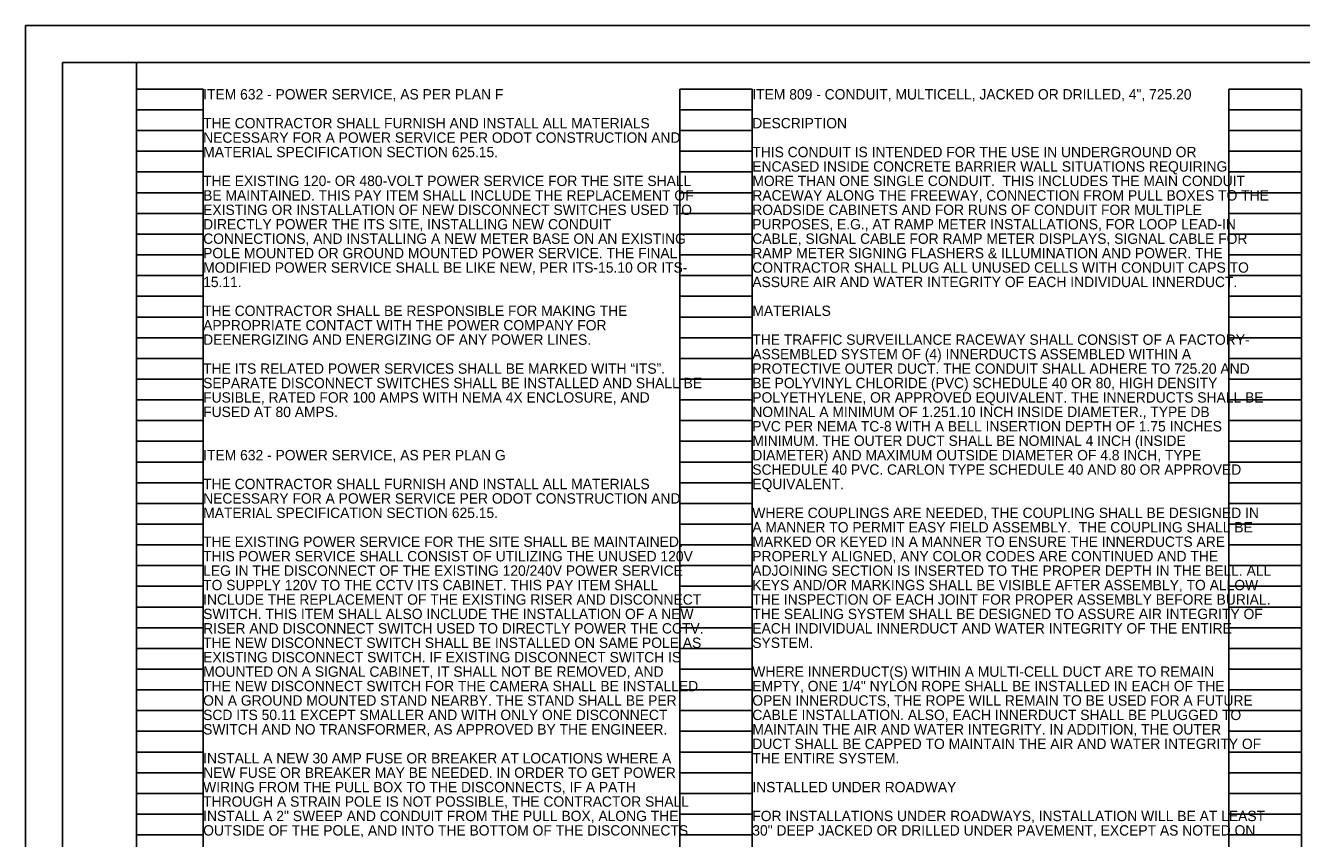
# Model space of a CAD drawing. Extents: x 0 to 34, y 0 to 22.
# Drawn here: x 0 to 17.24, y 11.01 to 22 of the extents above; entities that cross this region are included whole.
import ezdxf

# ---------------------------------------------------------------- set-up
doc = ezdxf.new("R2010")
doc.units = 0
for name, color, linetype in [('SH_Border', 7, 'Continuous'), ('SH_Cut_Line', 7, 'Continuous'), ('SH_Data', 7, 'Continuous'), ('SH_Text', 7, 'Continuous')]:
    doc.layers.add(name, color=color, linetype=linetype)

msp = doc.modelspace()

# ---------------------------------------------------------------- linework, layer by layer
at = {"layer": 'SH_Border'}
for points in [[(0.5, 21.5), (1.5, 21.5), (1.5, 0.5), (0.5, 0.5)], [(1.5, 21.5), (33.5, 21.5), (33.5, 0.5), (1.5, 0.5)]]:
    msp.add_lwpolyline(points, close=True, dxfattribs=at)
at = {"layer": 'SH_Cut_Line'}
msp.add_lwpolyline([(0, 0), (34, 0), (34, 22), (0, 22)], close=True, dxfattribs=at)
at = {"layer": 'SH_Data'}
for p, q in [((1.5, 0.98), (1.5, 21.14)), ((1.5, 21.14), (2.4, 21.14)), ((2.4, 0.98), (2.4, 21.14)), ((8.84, 0.98), (8.84, 21.14)), ((8.84, 21.14), (9.82, 21.14)), ((9.82, 0.98), (9.82, 21.14)), ((16.26, 0.98), (16.26, 21.14)), ((16.26, 21.14), (17.24, 21.14)), ((17.24, 0.98), (17.24, 21.14)), ((1.5, 20.86), (2.4, 20.86)), ((8.84, 20.86), (9.82, 20.86)), ((16.26, 20.86), (17.24, 20.86)), ((1.5, 20.58), (2.4, 20.58)), ((8.84, 20.58), (9.82, 20.58)), ((16.26, 20.58), (17.24, 20.58)), ((1.5, 20.3), (2.4, 20.3)), ((8.84, 20.3), (9.82, 20.3)), ((16.26, 20.3), (17.24, 20.3)), ((1.5, 20.02), (2.4, 20.02)), ((8.84, 20.02), (9.82, 20.02)), ((16.26, 20.02), (17.24, 20.02)), ((1.5, 19.74), (2.4, 19.74)), ((8.84, 19.74), (9.82, 19.74)), ((16.26, 19.74), (17.24, 19.74)), ((1.5, 19.46), (2.4, 19.46)), ((8.84, 19.46), (9.82, 19.46)), ((16.26, 19.46), (17.24, 19.46)), ((1.5, 19.18), (2.4, 19.18)), ((8.84, 19.18), (9.82, 19.18)), ((16.26, 19.18), (17.24, 19.18)), ((1.5, 18.9), (2.4, 18.9)), ((8.84, 18.9), (9.82, 18.9)), ((16.26, 18.9), (17.24, 18.9)), ((1.5, 18.62), (2.4, 18.62)), ((8.84, 18.62), (9.82, 18.62)), ((16.26, 18.62), (17.24, 18.62)), ((1.5, 18.34), (2.4, 18.34)), ((8.84, 18.34), (9.82, 18.34)), ((16.26, 18.34), (17.24, 18.34)), ((1.5, 18.06), (2.4, 18.06)), ((8.84, 18.06), (9.82, 18.06)), ((16.26, 18.06), (17.24, 18.06)), ((1.5, 17.78), (2.4, 17.78)), ((8.84, 17.78), (9.82, 17.78)), ((16.26, 17.78), (17.24, 17.78)), ((1.5, 17.5), (2.4, 17.5)), ((8.84, 17.5), (9.82, 17.5)), ((16.26, 17.5), (17.24, 17.5)), ((1.5, 17.22), (2.4, 17.22)), ((8.84, 17.22), (9.82, 17.22)), ((16.26, 17.22), (17.24, 17.22)), ((1.5, 16.94), (2.4, 16.94)), ((8.84, 16.94), (9.82, 16.94)), ((16.26, 16.94), (17.24, 16.94)), ((1.5, 16.66), (2.4, 16.66)), ((8.84, 16.66), (9.82, 16.66)), ((16.26, 16.66), (17.24, 16.66)), ((1.5, 16.38), (2.4, 16.38)), ((8.84, 16.38), (9.82, 16.38)), ((16.26, 16.38), (17.24, 16.38)), ((1.5, 16.1), (2.4, 16.1)), ((8.84, 16.1), (9.82, 16.1)), ((16.26, 16.1), (17.24, 16.1)), ((1.5, 15.82), (2.4, 15.82)), ((8.84, 15.82), (9.82, 15.82)), ((16.26, 15.82), (17.24, 15.82)), ((1.5, 15.54), (2.4, 15.54)), ((8.84, 15.54), (9.82, 15.54)), ((16.26, 15.54), (17.24, 15.54)), ((1.5, 15.26), (2.4, 15.26)), ((8.84, 15.26), (9.82, 15.26)), ((16.26, 15.26), (17.24, 15.26)), ((1.5, 14.98), (2.4, 14.98)), ((8.84, 14.98), (9.82, 14.98)), ((16.26, 14.98), (17.24, 14.98)), ((1.5, 14.7), (2.4, 14.7)), ((8.84, 14.7), (9.82, 14.7)), ((16.26, 14.7), (17.24, 14.7)), ((1.5, 14.42), (2.4, 14.42)), ((8.84, 14.42), (9.82, 14.42)), ((16.26, 14.42), (17.24, 14.42)), ((1.5, 14.14), (2.4, 14.14)), ((8.84, 14.14), (9.82, 14.14)), ((16.26, 14.14), (17.24, 14.14)), ((1.5, 13.86), (2.4, 13.86)), ((8.84, 13.86), (9.82, 13.86)), ((16.26, 13.86), (17.24, 13.86)), ((1.5, 13.58), (2.4, 13.58)), ((8.84, 13.58), (9.82, 13.58)), ((16.26, 13.58), (17.24, 13.58)), ((1.5, 13.3), (2.4, 13.3)), ((8.84, 13.3), (9.82, 13.3)), ((16.26, 13.3), (17.24, 13.3)), ((1.5, 13.02), (2.4, 13.02)), ((8.84, 13.02), (9.82, 13.02)), ((16.26, 13.02), (17.24, 13.02)), ((1.5, 12.74), (2.4, 12.74)), ((8.84, 12.74), (9.82, 12.74)), ((16.26, 12.74), (17.24, 12.74)), ((1.5, 12.46), (2.4, 12.46)), ((8.84, 12.46), (9.82, 12.46)), ((16.26, 12.46), (17.24, 12.46)), ((1.5, 12.18), (2.4, 12.18)), ((8.84, 12.18), (9.82, 12.18)), ((16.26, 12.18), (17.24, 12.18)), ((1.5, 11.9), (2.4, 11.9)), ((8.84, 11.9), (9.82, 11.9)), ((16.26, 11.9), (17.24, 11.9)), ((1.5, 11.62), (2.4, 11.62)), ((8.84, 11.62), (9.82, 11.62)), ((16.26, 11.62), (17.24, 11.62)), ((1.5, 11.34), (2.4, 11.34)), ((8.84, 11.34), (9.82, 11.34)), ((16.26, 11.34), (17.24, 11.34)), ((1.5, 11.06), (2.4, 11.06)), ((8.84, 11.06), (9.82, 11.06)), ((16.26, 11.06), (17.24, 11.06))]:
    msp.add_line(p, q, dxfattribs=at)

# ---------------------------------------------------------------- texts
at = {"layer": 'SH_Text'}
for s, p in [('ITEM 632 - POWER SERVICE, AS PER PLAN F', (2.4, 21)), ('ITEM 809 - CONDUIT, MULTICELL, JACKED OR DRILLED, 4", 725.20', (9.82, 21)), ('THE CONTRACTOR SHALL FURNISH AND INSTALL ALL MATERIALS ', (2.4, 20.61)), ('DESCRIPTION ', (9.82, 20.61)), ('NECESSARY FOR A POWER SERVICE PER ODOT CONSTRUCTION AND ', (2.4, 20.415)), ('MATERIAL SPECIFICATION SECTION 625.15. ', (2.4, 20.22)), ('THIS CONDUIT IS INTENDED FOR THE USE IN UNDERGROUND OR ', (9.82, 20.22)), ('ENCASED INSIDE CONCRETE BARRIER WALL SITUATIONS REQUIRING ', (9.82, 20.025)), ('THE EXISTING 120- OR 480-VOLT POWER SERVICE FOR THE SITE SHALL ', (2.4, 19.83)), ('MORE THAN ONE SINGLE CONDUIT.  THIS INCLUDES THE MAIN CONDUIT ', (9.82, 19.83)), ('BE MAINTAINED. THIS PAY ITEM SHALL INCLUDE THE REPLACEMENT OF ', (2.4, 19.634)), ('RACEWAY ALONG THE FREEWAY, CONNECTION FROM PULL BOXES TO THE ', (9.82, 19.634)), ('EXISTING OR INSTALLATION OF NEW DISCONNECT SWITCHES USED TO ', (2.4, 19.439)), ('ROADSIDE CABINETS AND FOR RUNS OF CONDUIT FOR MULTIPLE ', (9.82, 19.439)), ('DIRECTLY POWER THE ITS SITE, INSTALLING NEW CONDUIT ', (2.4, 19.244)), ('PURPOSES, E.G., AT RAMP METER INSTALLATIONS, FOR LOOP LEAD-IN ', (9.82, 19.244)), ('CONNECTIONS, AND INSTALLING A NEW METER BASE ON AN EXISTING ', (2.4, 19.049)), ('CABLE, SIGNAL CABLE FOR RAMP METER DISPLAYS, SIGNAL CABLE FOR ', (9.82, 19.049)), ('POLE MOUNTED OR GROUND MOUNTED POWER SERVICE. THE FINAL ', (2.4, 18.854)), ('RAMP METER SIGNING FLASHERS & ILLUMINATION AND POWER. THE ', (9.82, 18.854)), ('MODIFIED POWER SERVICE SHALL BE LIKE NEW, PER ITS-15.10 OR ITS-', (2.4, 18.659)), ('CONTRACTOR SHALL PLUG ALL UNUSED CELLS WITH CONDUIT CAPS TO ', (9.82, 18.659)), ('15.11.', (2.4, 18.464)), ('ASSURE AIR AND WATER INTEGRITY OF EACH INDIVIDUAL INNERDUCT.', (9.82, 18.464)), ('THE CONTRACTOR SHALL BE RESPONSIBLE FOR MAKING THE ', (2.4, 18.074)), ('MATERIALS ', (9.82, 18.074)), ('APPROPRIATE CONTACT WITH THE POWER COMPANY FOR ', (2.4, 17.879)), ('DEENERGIZING AND ENERGIZING OF ANY POWER LINES.', (2.4, 17.684)), ('THE TRAFFIC SURVEILLANCE RACEWAY SHALL CONSIST OF A FACTORY-', (9.82, 17.684)), ('ASSEMBLED SYSTEM OF (4) INNERDUCTS ASSEMBLED WITHIN A ', (9.82, 17.489)), ('THE ITS RELATED POWER SERVICES SHALL BE MARKED WITH “ITS”. ', (2.4, 17.293)), ('PROTECTIVE OUTER DUCT. THE CONDUIT SHALL ADHERE TO 725.20 AND ', (9.82, 17.293)), ('SEPARATE DISCONNECT SWITCHES SHALL BE INSTALLED AND SHALL BE ', (2.4, 17.098)), ('BE POLYVINYL CHLORIDE (PVC) SCHEDULE 40 OR 80, HIGH DENSITY ', (9.82, 17.098)), ('FUSIBLE, RATED FOR 100 AMPS WITH NEMA 4X ENCLOSURE, AND ', (2.4, 16.903)), ('POLYETHYLENE, OR APPROVED EQUIVALENT. THE INNERDUCTS SHALL BE ', (9.82, 16.903)), ('FUSED AT 80 AMPS.', (2.4, 16.708)), ('NOMINAL A MINIMUM OF 1.251.10 INCH INSIDE DIAMETER., TYPE DB ', (9.82, 16.708)), ('PVC PER NEMA TC-8 WITH A BELL INSERTION DEPTH OF 1.75 INCHES ', (9.82, 16.513)), ('MINIMUM. THE OUTER DUCT SHALL BE NOMINAL 4 INCH (INSIDE ', (9.82, 16.318)), ('ITEM 632 - POWER SERVICE, AS PER PLAN G', (2.4, 16.123)), ('DIAMETER) AND MAXIMUM OUTSIDE DIAMETER OF 4.8 INCH, TYPE ', (9.82, 16.123)), ('SCHEDULE 40 PVC. CARLON TYPE SCHEDULE 40 AND 80 OR APPROVED ', (9.82, 15.928)), ('THE CONTRACTOR SHALL FURNISH AND INSTALL ALL MATERIALS ', (2.4, 15.733)), ('EQUIVALENT.', (9.82, 15.733)), ('NECESSARY FOR A POWER SERVICE PER ODOT CONSTRUCTION AND ', (2.4, 15.538)), ('MATERIAL SPECIFICATION SECTION 625.15.', (2.4, 15.343)), ('WHERE COUPLINGS ARE NEEDED, THE COUPLING SHALL BE DESIGNED IN ', (9.82, 15.343)), ('A MANNER TO PERMIT EASY FIELD ASSEMBLY.  THE COUPLING SHALL BE ', (9.82, 15.148)), ('THE EXISTING POWER SERVICE FOR THE SITE SHALL BE MAINTAINED. ', (2.4, 14.953)), ('MARKED OR KEYED IN A MANNER TO ENSURE THE INNERDUCTS ARE ', (9.82, 14.953)), ('THIS POWER SERVICE SHALL CONSIST OF UTILIZING THE UNUSED 120V ', (2.4, 14.757)), ('PROPERLY ALIGNED, ANY COLOR CODES ARE CONTINUED AND THE ', (9.82, 14.757)), ('LEG IN THE DISCONNECT OF THE EXISTING 120/240V POWER SERVICE ', (2.4, 14.562)), ('ADJOINING SECTION IS INSERTED TO THE PROPER DEPTH IN THE BELL. ALL ', (9.82, 14.562)), ('TO SUPPLY 120V TO THE CCTV ITS CABINET. THIS PAY ITEM SHALL ', (2.4, 14.367)), ('KEYS AND/OR MARKINGS SHALL BE VISIBLE AFTER ASSEMBLY, TO ALLOW ', (9.82, 14.367)), ('INCLUDE THE REPLACEMENT OF THE EXISTING RISER AND DISCONNECT ', (2.4, 14.172)), ('THE INSPECTION OF EACH JOINT FOR PROPER ASSEMBLY BEFORE BURIAL. ', (9.82, 14.172)), ('SWITCH. THIS ITEM SHALL ALSO INCLUDE THE INSTALLATION OF A NEW ', (2.4, 13.977)), ('THE SEALING SYSTEM SHALL BE DESIGNED TO ASSURE AIR INTEGRITY OF ', (9.82, 13.977)), ('RISER AND DISCONNECT SWITCH USED TO DIRECTLY POWER THE CCTV. ', (2.4, 13.782)), ('EACH INDIVIDUAL INNERDUCT AND WATER INTEGRITY OF THE ENTIRE ', (9.82, 13.782)), ('THE NEW DISCONNECT SWITCH SHALL BE INSTALLED ON SAME POLE AS ', (2.4, 13.587)), ('SYSTEM.', (9.82, 13.587)), ('EXISTING DISCONNECT SWITCH. IF EXISTING DISCONNECT SWITCH IS ', (2.4, 13.392)), ('MOUNTED ON A SIGNAL CABINET, IT SHALL NOT BE REMOVED, AND ', (2.4, 13.197)), ('WHERE INNERDUCT(S) WITHIN A MULTI-CELL DUCT ARE TO REMAIN ', (9.82, 13.197)), ('THE NEW DISCONNECT SWITCH FOR THE CAMERA SHALL BE INSTALLED ', (2.4, 13.002)), ('EMPTY, ONE 1/4" NYLON ROPE SHALL BE INSTALLED IN EACH OF THE ', (9.82, 13.002)), ('ON A GROUND MOUNTED STAND NEARBY. THE STAND SHALL BE PER ', (2.4, 12.807)), ('OPEN INNERDUCTS, THE ROPE WILL REMAIN TO BE USED FOR A FUTURE ', (9.82, 12.807)), ('SCD ITS 50.11 EXCEPT SMALLER AND WITH ONLY ONE DISCONNECT ', (2.4, 12.612)), ('CABLE INSTALLATION. ALSO, EACH INNERDUCT SHALL BE PLUGGED TO ', (9.82, 12.612)), ('SWITCH AND NO TRANSFORMER, AS APPROVED BY THE ENGINEER.', (2.4, 12.417)), ('MAINTAIN THE AIR AND WATER INTEGRITY. IN ADDITION, THE OUTER ', (9.82, 12.417)), ('DUCT SHALL BE CAPPED TO MAINTAIN THE AIR AND WATER INTEGRITY OF ', (9.82, 12.221)), ('INSTALL A NEW 30 AMP FUSE OR BREAKER AT LOCATIONS WHERE A ', (2.4, 12.026)), ('THE ENTIRE SYSTEM.', (9.82, 12.026)), ('NEW FUSE OR BREAKER MAY BE NEEDED. IN ORDER TO GET POWER ', (2.4, 11.831)), ('WIRING FROM THE PULL BOX TO THE DISCONNECTS, IF A PATH ', (2.4, 11.636)), ('INSTALLED UNDER ROADWAY', (9.82, 11.636)), ('THROUGH A STRAIN POLE IS NOT POSSIBLE, THE CONTRACTOR SHALL ', (2.4, 11.441)), ('INSTALL A 2" SWEEP AND CONDUIT FROM THE PULL BOX, ALONG THE ', (2.4, 11.246)), ('FOR INSTALLATIONS UNDER ROADWAYS, INSTALLATION WILL BE AT LEAST ', (9.82, 11.246)), ('OUTSIDE OF THE POLE, AND INTO THE BOTTOM OF THE DISCONNECTS. ', (2.4, 11.051)), ('30" DEEP JACKED OR DRILLED UNDER PAVEMENT, EXCEPT AS NOTED ON ', (9.82, 11.051))]:
    msp.add_text(s, height=0.14, dxfattribs=at).set_placement(p)

doc.saveas('drawing.dxf')
